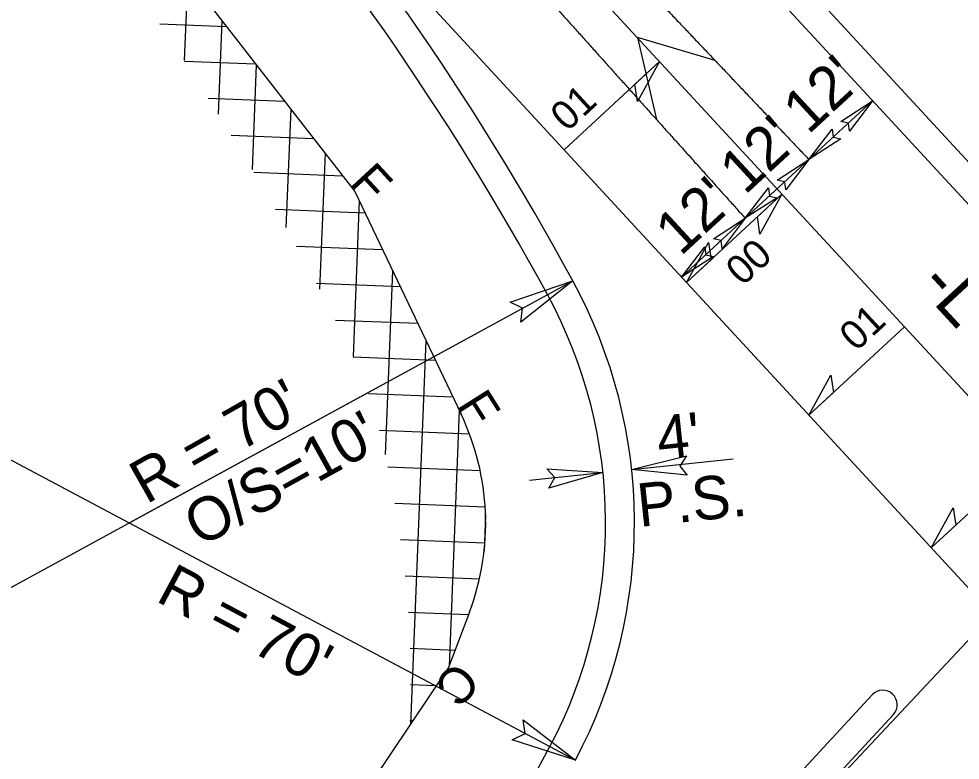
# Model space of a CAD drawing. Extents: x 1702862 to 1704514, y 793768 to 796215.
# Drawn here: x 1703186.2 to 1703316.6, y 795192.6 to 795295.2 of the extents above; entities that cross this region are included whole.
import ezdxf

# ---------------------------------------------------------------- set-up
doc = ezdxf.new("R2010")
doc.units = 0
for name, color, linetype in [('Prop Conc 5in Monolithic Surface Mount Island', 7, 'Continuous'), ('Prop Dimension', 7, 'Continuous'), ('Prop Dimension Text', 7, 'Continuous'), ('Prop EOT', 7, 'Continuous'), ('Prop Horizontal Alignment', 7, 'Continuous'), ('Prop Horizontal Alignment Direction Label', 7, 'Continuous'), ('Prop Lane Lines', 7, 'Continuous'), ('Prop Paint Stripe', 7, 'Continuous'), ('Prop Paved Shoulder', 7, 'Continuous'), ('Prop Rem of Exist Asph Pvmt', 7, 'Continuous'), ('Prop SS Cut Line', 7, 'Continuous'), ('Prop SS Fill Line', 7, 'Continuous'), ('Prop SS Misc', 7, 'Continuous'), ('Prop SS Transition Line', 7, 'Continuous'), ('Prop Superelevation  Arrow CELL', 7, 'Continuous'), ('Prop Superelevation Label', 7, 'Continuous'), ('Prop Terminator CELL', 7, 'Continuous')]:
    doc.layers.add(name, color=color, linetype=linetype)

msp = doc.modelspace()

# ---------------------------------------------------------------- linework, layer by layer
at = {"layer": 'Prop Conc 5in Monolithic Surface Mount Island'}
for p, q in [((1703304.39, 795201.63), (1703263.21, 795157.11)), ((1703304.39, 795201.63), (1703263.21, 795157.11)), ((1703266.15, 795154.39), (1703307.33, 795198.91)), ((1703266.15, 795154.39), (1703307.33, 795198.91))]:
    msp.add_line(p, q, dxfattribs=at)
msp.add_arc((1703305.86, 795200.27), 2, 317.2317, 137.2317, dxfattribs=at)
msp.add_arc((1703305.86, 795200.27), 2, 317.2317, 137.2317, dxfattribs=at)
at = {"layer": 'Prop Dimension'}
for p, q in [((1702910.07, 795380.31), (1703263.28, 795192.59)), ((1703295.63, 795275.75), (1703304.45, 795283.89)), ((1703286.82, 795267.61), (1703295.63, 795275.75)), ((1703278, 795259.47), (1703286.82, 795267.61)), ((1702911.8, 795067.36), (1703262.92, 795258.97)), ((1703201.47, 795225.44), (1703262.92, 795258.97)), ((1703271.07, 795232.84), (1703285.15, 795234.33)), ((1703256.95, 795231.34), (1703267.09, 795232.42)), ((1703201.47, 795225.44), (1703263.28, 795192.59))]:
    msp.add_line(p, q, dxfattribs=at)
at = {"layer": 'Prop EOT'}
msp.add_line((1703259.9, 795332.15), (1703737.14, 794815.13), dxfattribs=at)
for centre, radius, start, end in [((1702911.8, 795067.36), 400, 28.6224, 41.0304), ((1703201.47, 795225.44), 70, 332.0106, 28.6224)]:
    msp.add_arc(centre, radius, start, end, dxfattribs=at)
at = {"layer": 'Prop Horizontal Alignment'}
for p, q in [((1703246.67, 795319.94), (1703723.92, 794802.92)), ((1703333.42, 795225.96), (1703157.53, 795038.5))]:
    msp.add_line(p, q, dxfattribs=at)
at = {"layer": 'Prop Lane Lines'}
msp.add_line((1703233.45, 795307.73), (1703333.8, 795199.01), dxfattribs=at)
for points in [[(1703251.4, 795322.4), (1703252, 795321.77), (1703252.6, 795321.14), (1703253.19, 795320.51), (1703253.79, 795319.88), (1703254.39, 795319.25), (1703254.99, 795318.62), (1703255.59, 795317.99), (1703256.18, 795317.36), (1703256.78, 795316.73), (1703257.38, 795316.1), (1703257.98, 795315.47), (1703258.57, 795314.84), (1703259.17, 795314.21), (1703259.77, 795313.58), (1703260.37, 795312.95), (1703260.96, 795312.31), (1703261.56, 795311.68), (1703262.16, 795311.05), (1703262.76, 795310.42), (1703263.36, 795309.79), (1703263.95, 795309.16), (1703264.55, 795308.53), (1703265.15, 795307.9), (1703265.75, 795307.27), (1703266.34, 795306.64), (1703266.94, 795306.01), (1703267.54, 795305.38), (1703268.14, 795304.75), (1703268.74, 795304.12), (1703269.33, 795303.49), (1703269.93, 795302.86), (1703270.53, 795302.23), (1703271.13, 795301.6), (1703271.72, 795300.97), (1703272.32, 795300.34), (1703272.92, 795299.71), (1703273.52, 795299.07), (1703274.12, 795298.44), (1703274.71, 795297.81), (1703275.31, 795297.18), (1703275.91, 795296.55), (1703276.51, 795295.92), (1703277.1, 795295.29), (1703277.7, 795294.66), (1703278.3, 795294.03), (1703278.9, 795293.4), (1703279.49, 795292.77), (1703280.09, 795292.14), (1703280.69, 795291.51), (1703281.29, 795290.88), (1703281.89, 795290.25), (1703282.48, 795289.62), (1703283.08, 795288.99), (1703283.68, 795288.36), (1703284.28, 795287.73), (1703284.87, 795287.1), (1703285.47, 795286.46), (1703286.07, 795285.83), (1703286.67, 795285.2), (1703287.27, 795284.57), (1703287.86, 795283.94), (1703288.46, 795283.31), (1703289.06, 795282.68), (1703289.66, 795282.05), (1703290.25, 795281.42), (1703290.85, 795280.79), (1703291.45, 795280.16), (1703292.05, 795279.53), (1703292.65, 795278.9), (1703293.24, 795278.27), (1703293.84, 795277.64), (1703294.44, 795277.01), (1703295.63, 795275.75)], [(1703243.84, 795315.43), (1703244.42, 795314.78), (1703245, 795314.13), (1703245.59, 795313.49), (1703246.17, 795312.84), (1703246.75, 795312.2), (1703247.33, 795311.55), (1703247.91, 795310.9), (1703248.49, 795310.26), (1703249.07, 795309.61), (1703249.65, 795308.96), (1703250.23, 795308.32), (1703250.81, 795307.67), (1703251.39, 795307.03), (1703251.97, 795306.38), (1703252.55, 795305.73), (1703253.13, 795305.09), (1703253.72, 795304.44), (1703254.3, 795303.79), (1703254.88, 795303.15), (1703255.46, 795302.5), (1703256.04, 795301.86), (1703256.62, 795301.21), (1703257.2, 795300.56), (1703257.78, 795299.92), (1703258.36, 795299.27), (1703258.94, 795298.62), (1703259.52, 795297.98), (1703260.1, 795297.33), (1703260.68, 795296.69), (1703261.26, 795296.04), (1703261.85, 795295.39), (1703262.43, 795294.75), (1703263.01, 795294.1), (1703263.59, 795293.46), (1703264.17, 795292.81), (1703264.75, 795292.16), (1703265.33, 795291.52), (1703265.91, 795290.87), (1703266.49, 795290.22), (1703267.07, 795289.58), (1703267.65, 795288.93), (1703268.23, 795288.29), (1703268.81, 795287.64), (1703269.39, 795286.99), (1703269.98, 795286.35), (1703270.56, 795285.7), (1703271.14, 795285.05), (1703271.72, 795284.41), (1703272.3, 795283.76), (1703272.88, 795283.12), (1703273.46, 795282.47), (1703274.04, 795281.82), (1703274.62, 795281.18), (1703275.2, 795280.53), (1703275.78, 795279.88), (1703276.36, 795279.24), (1703276.94, 795278.59), (1703277.52, 795277.95), (1703278.11, 795277.3), (1703278.69, 795276.65), (1703279.27, 795276.01), (1703279.85, 795275.36), (1703280.43, 795274.72), (1703281.01, 795274.07), (1703281.59, 795273.42), (1703282.17, 795272.78), (1703282.75, 795272.13), (1703283.33, 795271.48), (1703283.91, 795270.84), (1703284.49, 795270.19), (1703285.07, 795269.55), (1703285.65, 795268.9), (1703286.82, 795267.61)]]:
    msp.add_spline(points, degree=3, dxfattribs=at)
at = {"layer": 'Prop Paint Stripe'}
for p, q in [((1703282.66, 795289.44), (1703271.88, 795292.64)), ((1703271.88, 795292.64), (1703274.54, 795281.27)), ((1703295.63, 795275.75), (1703286.82, 795267.61))]:
    msp.add_line(p, q, dxfattribs=at)
for points in [[(1703251.4, 795322.4), (1703252, 795321.77), (1703252.6, 795321.14), (1703253.19, 795320.51), (1703253.79, 795319.88), (1703254.39, 795319.25), (1703254.99, 795318.62), (1703255.59, 795317.99), (1703256.18, 795317.36), (1703256.78, 795316.73), (1703257.38, 795316.1), (1703257.98, 795315.47), (1703258.57, 795314.84), (1703259.17, 795314.21), (1703259.77, 795313.58), (1703260.37, 795312.95), (1703260.96, 795312.31), (1703261.56, 795311.68), (1703262.16, 795311.05), (1703262.76, 795310.42), (1703263.36, 795309.79), (1703263.95, 795309.16), (1703264.55, 795308.53), (1703265.15, 795307.9), (1703265.75, 795307.27), (1703266.34, 795306.64), (1703266.94, 795306.01), (1703267.54, 795305.38), (1703268.14, 795304.75), (1703268.74, 795304.12), (1703269.33, 795303.49), (1703269.93, 795302.86), (1703270.53, 795302.23), (1703271.13, 795301.6), (1703271.72, 795300.97), (1703272.32, 795300.34), (1703272.92, 795299.71), (1703273.52, 795299.07), (1703274.12, 795298.44), (1703274.71, 795297.81), (1703275.31, 795297.18), (1703275.91, 795296.55), (1703276.51, 795295.92), (1703277.1, 795295.29), (1703277.7, 795294.66), (1703278.3, 795294.03), (1703278.9, 795293.4), (1703279.49, 795292.77), (1703280.09, 795292.14), (1703280.69, 795291.51), (1703281.29, 795290.88), (1703281.89, 795290.25), (1703282.48, 795289.62), (1703283.08, 795288.99), (1703283.68, 795288.36), (1703284.28, 795287.73), (1703284.87, 795287.1), (1703285.47, 795286.46), (1703286.07, 795285.83), (1703286.67, 795285.2), (1703287.27, 795284.57), (1703287.86, 795283.94), (1703288.46, 795283.31), (1703289.06, 795282.68), (1703289.66, 795282.05), (1703290.25, 795281.42), (1703290.85, 795280.79), (1703291.45, 795280.16), (1703292.05, 795279.53), (1703292.65, 795278.9), (1703293.24, 795278.27), (1703293.84, 795277.64), (1703294.44, 795277.01), (1703295.63, 795275.75)], [(1703243.84, 795315.43), (1703244.42, 795314.78), (1703245, 795314.13), (1703245.59, 795313.49), (1703246.17, 795312.84), (1703246.75, 795312.2), (1703247.33, 795311.55), (1703247.91, 795310.9), (1703248.49, 795310.26), (1703249.07, 795309.61), (1703249.65, 795308.96), (1703250.23, 795308.32), (1703250.81, 795307.67), (1703251.39, 795307.03), (1703251.97, 795306.38), (1703252.55, 795305.73), (1703253.13, 795305.09), (1703253.72, 795304.44), (1703254.3, 795303.79), (1703254.88, 795303.15), (1703255.46, 795302.5), (1703256.04, 795301.86), (1703256.62, 795301.21), (1703257.2, 795300.56), (1703257.78, 795299.92), (1703258.36, 795299.27), (1703258.94, 795298.62), (1703259.52, 795297.98), (1703260.1, 795297.33), (1703260.68, 795296.69), (1703261.26, 795296.04), (1703261.85, 795295.39), (1703262.43, 795294.75), (1703263.01, 795294.1), (1703263.59, 795293.46), (1703264.17, 795292.81), (1703264.75, 795292.16), (1703265.33, 795291.52), (1703265.91, 795290.87), (1703266.49, 795290.22), (1703267.07, 795289.58), (1703267.65, 795288.93), (1703268.23, 795288.29), (1703268.81, 795287.64), (1703269.39, 795286.99), (1703269.98, 795286.35), (1703270.56, 795285.7), (1703271.14, 795285.05), (1703271.72, 795284.41), (1703272.3, 795283.76), (1703272.88, 795283.12), (1703273.46, 795282.47), (1703274.04, 795281.82), (1703274.62, 795281.18), (1703275.2, 795280.53), (1703275.78, 795279.88), (1703276.36, 795279.24), (1703276.94, 795278.59), (1703277.52, 795277.95), (1703278.11, 795277.3), (1703278.69, 795276.65), (1703279.27, 795276.01), (1703279.85, 795275.36), (1703280.43, 795274.72), (1703281.01, 795274.07), (1703281.59, 795273.42), (1703282.17, 795272.78), (1703282.75, 795272.13), (1703283.33, 795271.48), (1703283.91, 795270.84), (1703284.49, 795270.19), (1703285.07, 795269.55), (1703285.65, 795268.9), (1703286.82, 795267.61)]]:
    msp.add_spline(points, degree=3, dxfattribs=at)
at = {"layer": 'Prop Paved Shoulder'}
msp.add_line((1703262.84, 795334.86), (1703385.95, 795201.5), dxfattribs=at)
for centre, radius, start, end in [((1702911.8, 795067.36), 396, 28.6224, 41.0304), ((1703201.47, 795225.44), 66, 332.0106, 28.6224), ((1702910.07, 795380.31), 396, 322.1318, 332.0106)]:
    msp.add_arc(centre, radius, start, end, dxfattribs=at)
at = {"layer": 'Prop Rem of Exist Asph Pvmt'}
for p, q in [((1703209.58, 795301.09), (1703209.11, 795289.44)), ((1703205.72, 795294.53), (1703214.96, 795294.16)), ((1703214.33, 795294.97), (1703213.82, 795282.04)), ((1703209.14, 795289.39), (1703218.98, 795289)), ((1703219.09, 795288.86), (1703218.51, 795274.38)), ((1703212.42, 795284.26), (1703223, 795283.84)), ((1703223.85, 795282.74), (1703223.2, 795266.35)), ((1703215.63, 795279.13), (1703227.01, 795278.67)), ((1703228.61, 795276.62), (1703227.86, 795257.79)), ((1703218.74, 795274), (1703231.03, 795273.51)), ((1703233.35, 795270.03), (1703232.49, 795248.49)), ((1703221.75, 795268.87), (1703234.14, 795268.38)), ((1703224.65, 795263.75), (1703236.58, 795263.28)), ((1703237.97, 795260.36), (1703236.95, 795234.91)), ((1703227.41, 795258.64), (1703239.01, 795258.17)), ((1703230.04, 795253.53), (1703241.45, 795253.07)), ((1703242.59, 795250.69), (1703240.46, 795197.58)), ((1703232.52, 795248.43), (1703243.88, 795247.97)), ((1703234.61, 795243.34), (1703246.32, 795242.87)), ((1703247.2, 795241.02), (1703245.79, 795205.57)), ((1703236.15, 795238.27), (1703248.61, 795237.77)), ((1703237.31, 795233.22), (1703250.1, 795232.71)), ((1703238.26, 795228.18), (1703250.79, 795227.68)), ((1703250.85, 795226.54), (1703250.64, 795221.53)), ((1703239.08, 795223.14), (1703250.69, 795222.68)), ((1703239.73, 795218.11), (1703250, 795217.7)), ((1703240.18, 795213.09), (1703248.49, 795212.76)), ((1703240.42, 795208.08), (1703246.64, 795207.83)), ((1703240.46, 795203.07), (1703244.06, 795202.93)), ((1703240.35, 795198.07), (1703240.78, 795198.06))]:
    msp.add_line(p, q, dxfattribs=at)
at = {"layer": 'Prop SS Cut Line'}
msp.add_line((1703245.72, 795205.41), (1703231.59, 795184.39), dxfattribs=at)
at = {"layer": 'Prop SS Fill Line'}
msp.add_line((1703232.75, 795271.3), (1703247.45, 795240.51), dxfattribs=at)
at = {"layer": 'Prop SS Transition Line'}
for p, q in [((1703201.37, 795311.64), (1703232.75, 795271.3)), ((1703248.62, 795213.1), (1703245.72, 795205.41))]:
    msp.add_line(p, q, dxfattribs=at)
msp.add_arc((1703215.86, 795225.43), 35, 339.3736, 25.5202, dxfattribs=at)
at = {"layer": 'Prop Superelevation  Arrow CELL'}
for p, q in [((1703274.94, 795289.32), (1703261.71, 795277.11)), ((1703291.89, 795270.95), (1703278.67, 795258.74)), ((1703308.85, 795252.58), (1703295.63, 795240.37)), ((1703325.81, 795234.21), (1703312.58, 795222))]:
    msp.add_line(p, q, dxfattribs=at)
for points in [[(1703274.94, 795289.32), (1703271.89, 795283.78), (1703271.54, 795286.18)], [(1703291.89, 795270.95), (1703288.84, 795265.41), (1703288.5, 795267.81)], [(1703278.67, 795258.74), (1703281.72, 795264.28), (1703282.07, 795261.88)], [(1703295.63, 795240.37), (1703298.68, 795245.91), (1703299.02, 795243.51)], [(1703312.58, 795222), (1703315.63, 795227.54), (1703315.98, 795225.14)]]:
    msp.add_lwpolyline(points, close=True, dxfattribs=at)
at = {"layer": 'Prop Terminator CELL'}
for points in [[(1703300.04, 795281.03), (1703304.45, 795283.89), (1703301.25, 795279.68), (1703301.11, 795280.8)], [(1703300.04, 795278.6), (1703295.63, 795275.75), (1703298.83, 795279.95), (1703298.97, 795278.83)], [(1703291.23, 795272.89), (1703295.63, 795275.75), (1703292.43, 795271.54), (1703292.3, 795272.67)], [(1703291.22, 795270.46), (1703286.82, 795267.61), (1703290.02, 795271.81), (1703290.15, 795270.69)], [(1703282.41, 795264.75), (1703286.82, 795267.61), (1703283.62, 795263.4), (1703283.48, 795264.53)], [(1703282.41, 795262.32), (1703278, 795259.47), (1703281.2, 795263.67), (1703281.34, 795262.55)], [(1703254.27, 795256.02), (1703262.92, 795258.97), (1703255.74, 795253.23), (1703255.98, 795255.19)], [(1703278.79, 795232.03), (1703271.07, 795232.84), (1703278.66, 795234.71), (1703277.77, 795233.28)], [(1703259.35, 795232.92), (1703267.09, 795232.42), (1703259.59, 795230.25), (1703260.42, 795231.71)], [(1703256.06, 795198.18), (1703263.28, 795192.59), (1703254.54, 795195.42), (1703256.31, 795196.29)]]:
    msp.add_lwpolyline(points, close=True, dxfattribs=at)

# ---------------------------------------------------------------- texts
at = {"layer": 'Prop Dimension'}
for s, rotation, p in [("O/S=10'", 28.8804, (1703211.3, 795222)), ("4'", 6.0681, (1703274.88, 795234.21)), ('P.S.', 6.0681, (1703272.17, 795224.87))]:
    msp.add_text(s, height=6, rotation=rotation, dxfattribs=at).set_placement(p)
at = {"layer": 'Prop Dimension Text'}
for s, rotation, p in [("12'", 42.7091, (1703295.53, 795279.1)), ("12'", 42.7091, (1703286.76, 795270.75)), ("12'", 42.7091, (1703277.85, 795262.27)), ("R = 70'", 29.433, (1703203.85, 795227.96)), ("R = 70'", 332.0106, (1703205, 795214.7))]:
    msp.add_text(s, height=6, rotation=rotation, dxfattribs=at).set_placement(p)
at = {"layer": 'Prop Horizontal Alignment Direction Label'}
msp.add_text('-L-', height=7, rotation=312.7091, dxfattribs=at).set_placement((1703310.6, 795258.2))
at = {"layer": 'Prop SS Misc'}
for s, rotation, p in [('F', 312.7091, (1703231.79, 795272.34)), ('F', 302.2972, (1703246.69, 795241.71)), ('C', 226.823, (1703246.77, 795206.53))]:
    msp.add_text(s, height=5, rotation=rotation, dxfattribs=at).set_placement(p)
at = {"layer": 'Prop Superelevation Label'}
for s, p in [('01', (1703262.14, 795279.48)), ('00', (1703286.43, 795258.12)), ('01', (1703302.17, 795249.06))]:
    msp.add_text(s, height=4, rotation=42.7091, dxfattribs=at).set_placement(p)

doc.saveas('drawing.dxf')
